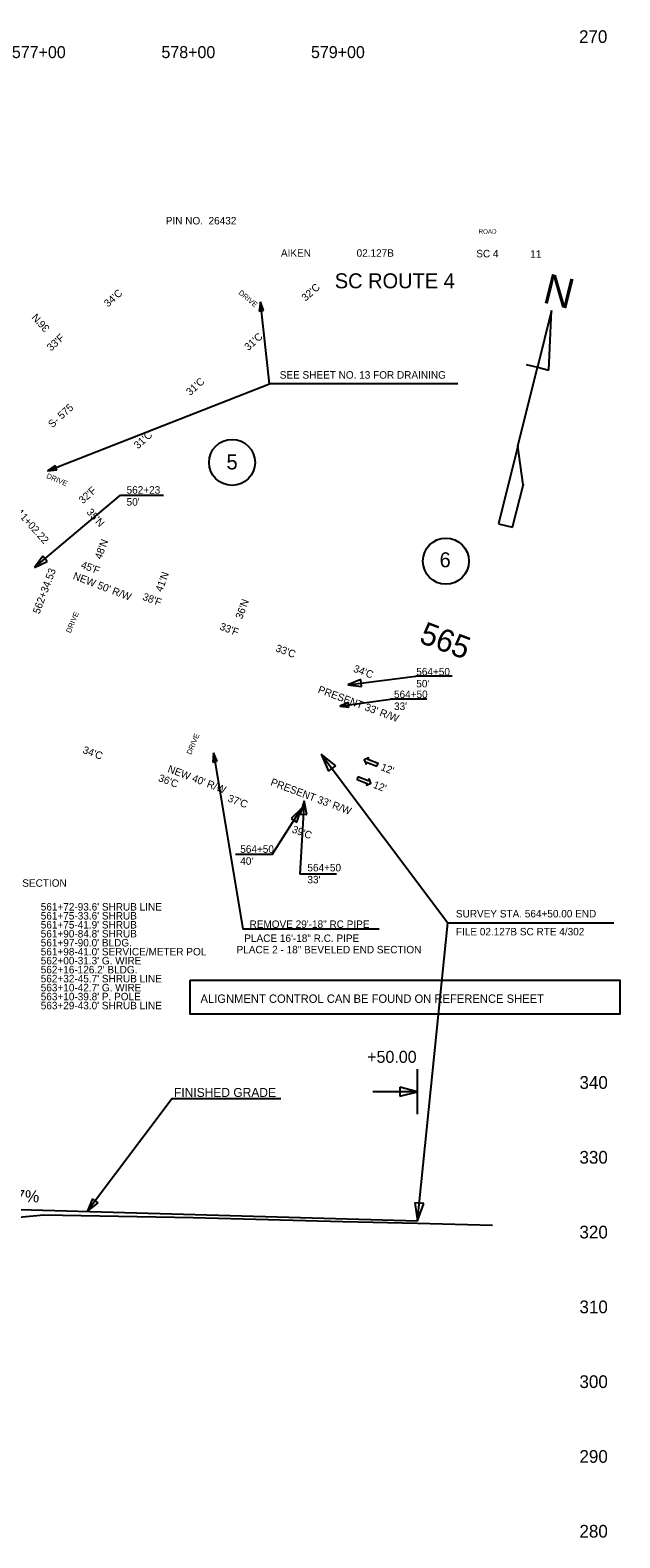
# Model space of a CAD drawing. Extents: x 48556 to 51363, y 45290 to 53458.
# Drawn here: x 50379 to 50773, y 51425 to 52433 of the extents above; entities that cross this region are included whole.
import ezdxf

# ---------------------------------------------------------------- set-up
doc = ezdxf.new("R2010")
doc.units = 0
for name, color, linetype in [('Level 1', 7, 'Continuous'), ('Level 12', 7, 'Continuous'), ('Level 14', 7, 'Continuous'), ('Level 19', 7, 'Continuous'), ('Level 2', 7, 'Continuous'), ('Level 20', 7, 'Continuous'), ('Level 21', 7, 'Continuous'), ('Level 24', 7, 'Continuous'), ('Level 25', 7, 'Continuous'), ('Level 29', 7, 'Continuous'), ('Level 33', 7, 'Continuous'), ('Level 40', 7, 'Continuous'), ('Level 41', 7, 'Continuous'), ('Level 42', 7, 'Continuous'), ('Level 45', 7, 'Continuous'), ('Level 48', 7, 'Continuous'), ('Level 6', 7, 'Continuous'), ('Level 8', 7, 'Continuous')]:
    doc.layers.add(name, color=color, linetype=linetype)

msp = doc.modelspace()

# ---------------------------------------------------------------- linework, layer by layer
at = {"layer": 'Level 1'}
for p, q in [((50573.5, 51948.5), (50658.2, 51835.8)), ((50637.9, 51636.5), (50658.2, 51835.8)), ((50658.2, 51835.8), (50769.1, 51835.8)), ((50637.9, 51707.9), (50637.9, 51737.9)), ((50473.7, 51718.3), (50417, 51642.7)), ((50473.7, 51718.3), (50546.5, 51718.3)), ((50637.9, 51722.9), (50607.9, 51722.9))]:
    msp.add_line(p, q, dxfattribs=at)
at = {"layer": 'Level 12'}
for centre in [(50513.8, 52143.6), (50656.8, 52077.6)]:
    msp.add_circle(centre, 15.4, dxfattribs=at)
at = {"layer": 'Level 14'}
for points in [[(50610.7, 51940.6), (50611.4, 51942.4), (50604.5, 51945), (50605, 51946.2), (50602.1, 51944.8), (50603.4, 51941.9), (50603.8, 51943.2)], [(50598, 51933.4), (50597.4, 51931.6), (50604.2, 51929), (50603.8, 51927.8), (50606.7, 51929.1), (50605.4, 51932.1), (50604.9, 51930.8)]]:
    msp.add_lwpolyline(points, close=True, dxfattribs=at)
at = {"layer": 'Level 2'}
for p, q in [((50727.5, 52245.2), (50718, 52207.2)), ((50725.6, 52205.3), (50727.5, 52245.2)), ((50727.5, 52245.2), (50727.5, 52245.2)), ((50704.8, 52154.4), (50718, 52207.2)), ((50710.4, 52209.1), (50718, 52207.2)), ((50718, 52207.2), (50725.6, 52205.3)), ((50725.6, 52205.3), (50725.7, 52205.7)), ((50704.8, 52154.4), (50691.9, 52102.6)), ((50708.5, 52128.7), (50704.8, 52154.4)), ((50701.4, 52100.2), (50708.6, 52129)), ((50708.6, 52129), (50708.5, 52128.7)), ((50691.9, 52102.6), (50701.4, 52100.2))]:
    msp.add_line(p, q, dxfattribs=at)
at = {"layer": 'Level 24'}
for p, q in [((50532.8, 52250.9), (50531.9, 52244.8)), ((50531.9, 52244.8), (50534.9, 52245.1)), ((50534.9, 52245.1), (50532.8, 52250.9)), ((50395.6, 52141.5), (50390.5, 52137.9)), ((50396.7, 52138.7), (50395.6, 52141.5)), ((50390.5, 52137.9), (50396.7, 52138.7)), ((50387.2, 52080.9), (50381.8, 52073.4)), ((50390.1, 52077.4), (50387.2, 52080.9)), ((50381.8, 52073.4), (50390.1, 52077.4)), ((50599.9, 51998.4), (50591.2, 51995)), ((50599.9, 51998.4), (50591.2, 51995)), ((50591.2, 51995), (50600.4, 51993.9)), ((50591.2, 51995), (50600.4, 51993.9)), ((50600.4, 51993.9), (50599.9, 51998.4)), ((50600.4, 51993.9), (50599.9, 51998.4)), ((50591.6, 51983), (50585.8, 51980.7)), ((50585.8, 51980.7), (50592, 51980)), ((50592, 51980), (50591.6, 51983)), ((50501.4, 51949.5), (50500.9, 51943.3)), ((50503.9, 51943.8), (50501.4, 51949.5)), ((50500.9, 51943.3), (50503.9, 51943.8)), ((50573.5, 51948.5), (50578.3, 51937.1)), ((50583.1, 51940.7), (50573.5, 51948.5)), ((50578.3, 51937.1), (50583.1, 51940.7)), ((50560.1, 51911.9), (50553.4, 51905.6)), ((50557.2, 51903.2), (50560.1, 51911.9)), ((50562.1, 51917.3), (50559.3, 51908.5)), ((50563.8, 51908.2), (50562.1, 51917.3)), ((50553.4, 51905.6), (50557.2, 51903.2)), ((50559.3, 51908.5), (50563.8, 51908.2)), ((50637.9, 51722.9), (50625.9, 51725.9)), ((50625.9, 51725.9), (50625.9, 51719.9)), ((50625.9, 51719.9), (50637.9, 51722.9)), ((50420.6, 51651.3), (50417, 51642.7)), ((50417, 51642.7), (50424.2, 51648.6)), ((50424.2, 51648.6), (50420.6, 51651.3)), ((50642.1, 51648.1), (50636.1, 51648.7)), ((50636.1, 51648.7), (50637.9, 51636.5)), ((50637.9, 51636.5), (50642.1, 51648.1))]:
    msp.add_line(p, q, dxfattribs=at)
at = {"layer": 'Level 25'}
msp.add_lwpolyline([(50485.8, 51797.4), (50773.1, 51797.4), (50773.1, 51774.7), (50485.8, 51774.7)], close=True, dxfattribs=at)
at = {"layer": 'Level 33'}
for p, q in [((50381.8, 52073.4), (50439.2, 52121.8)), ((50439.2, 52121.8), (50468, 52121.8)), ((50591.2, 51995), (50636.6, 52000.6)), ((50661, 52000.6), (50636.6, 52000.6)), ((50585.8, 51980.7), (50619.7, 51985.3)), ((50644.1, 51985.3), (50619.7, 51985.3)), ((50540.6, 51881.5), (50560.1, 51911.9)), ((50562.1, 51917.3), (50559.1, 51868.4)), ((50540.6, 51881.5), (50516.2, 51881.5)), ((50583.6, 51868.4), (50559.1, 51868.4))]:
    msp.add_line(p, q, dxfattribs=at)
at = {"layer": 'Level 40'}
msp.add_lwpolyline([(49737.9, 51618.4), (49787.9, 51629.6), (49837.9, 51637.9), (49887.9, 51643.8), (49937.9, 51647.2), (49987.9, 51648), (50037.9, 51647.7), (50087.9, 51654.7), (50137.9, 51645.6), (50187.9, 51644.3), (50237.9, 51643.2), (50287.9, 51642.5), (50305.6, 51639.5), (50351.8, 51637.3), (50387.9, 51640.6), (50437.9, 51639.7), (50487.9, 51638.8), (50537.9, 51637.5), (50587.9, 51636.2), (50637.9, 51635), (50687.9, 51633.7)], dxfattribs=at)
at = {"layer": 'Level 45'}
msp.add_line((50314.1, 51645.7), (50637.9, 51636.5), dxfattribs=at)
at = {"layer": 'Level 6'}
for p, q in [((50538.9, 52196.1), (50532.8, 52250.9)), ((50390.5, 52137.9), (50538.9, 52196.1)), ((50664.7, 52196.1), (50538.9, 52196.1)), ((50501.4, 51949.5), (50521.1, 51831.6)), ((50612.1, 51831.6), (50521.1, 51831.6))]:
    msp.add_line(p, q, dxfattribs=at)

# ---------------------------------------------------------------- texts
at = {"layer": 'Level 1'}
for p in [(50570.8, 51989.8), (50539.1, 51927.9)]:
    msp.add_text("PRESENT 33' R/W", height=5, rotation=339.4944, dxfattribs=at).set_placement(p)
for s, height, p in [('SURVEY STA. 564+50.00 END', 5, (50663.5, 51839.4)), ('FILE 02.127B SC RTE 4/302', 5, (50663.5, 51827.4)), ('+50.00', 8, (50604.2, 51742.2)), ('FINISHED GRADE', 6, (50475, 51719.4))]:
    msp.add_text(s, height=height, dxfattribs=at).set_placement(p)
at = {"layer": 'Level 12'}
for s, p in [('5', (50510.1, 52138.9)), ('6', (50652.6, 52073.5))]:
    msp.add_text(s, height=10, dxfattribs=at).set_placement(p)
at = {"layer": 'Level 19'}
msp.add_text('565', height=15, rotation=339.4944, dxfattribs=at).set_placement((50638.2, 52023.4))
at = {"layer": 'Level 2'}
msp.add_text('N', height=20, rotation=346, dxfattribs=at).set_placement((50720.7, 52250.7))
at = {"layer": 'Level 20'}
for s, rotation, p in [('11+02.22', 311.9794, (50369.3, 52109.6)), ('562+34.53', 69.4943, (50385, 52041.9)), ("12'", 339.1234, (50612.8, 51938)), ("12'", 339.1234, (50607.7, 51926.2))]:
    msp.add_text(s, height=5, rotation=rotation, dxfattribs=at).set_placement(p)
at = {"layer": 'Level 21'}
msp.add_text('S- 575', height=5, rotation=42.1456, dxfattribs=at).set_placement((50393.6, 52166.4))
at = {"layer": 'Level 24'}
for s, height, p in [('PIN NO.  26432', 5, (50469.5, 52302.7)), ('ROAD', 3, (50678.7, 52296.5)), ('AIKEN', 5, (50546.5, 52281.1)), ('02.127B', 5, (50597.1, 52281.1)), ('SC 4', 5, (50677.1, 52280.7)), ('11', 5, (50713.2, 52280.4)), ('SC ROUTE 4', 10, (50582.5, 52260)), ("561+72-93.6' SHRUB LINE", 5, (50385.9, 51844)), ("561+75-33.6' SHRUB", 5, (50385.9, 51838)), ("561+75-41.9' SHRUB", 5, (50385.9, 51832)), ("561+90-84.8' SHRUB", 5, (50385.9, 51826)), ("561+97-90.0' BLDG.", 5, (50385.9, 51820)), ("561+98-41.0' SERVICE/METER POL", 5, (50385.9, 51814)), ("562+00-31.3' G. WIRE", 5, (50385.9, 51808)), ("562+16-126.2' BLDG.", 5, (50385.9, 51802)), ("562+32-45.7' SHRUB LINE", 5, (50385.9, 51796)), ("563+10-42.7' G. WIRE", 5, (50385.9, 51790)), ("563+10-39.8' P. POLE", 5, (50385.9, 51784)), ("563+29-43.0' SHRUB LINE", 5, (50385.9, 51778))]:
    msp.add_text(s, height=height, dxfattribs=at).set_placement(p)
at = {"layer": 'Level 25'}
msp.add_text('ALIGNMENT CONTROL CAN BE FOUND ON REFERENCE SHEET', height=5.6, dxfattribs=at).set_placement((50492.7, 51782.3))
at = {"layer": 'Level 29'}
for s, p in [(' PLACE 2 - 18" BEVELED END SECTION', (50277.9, 51859.9)), (' PLACE 2 - 18" BEVELED END SECTION', (50515, 51815.4)), ('PLACE 16\'-18" R.C. PIPE', (50522, 51823))]:
    msp.add_text(s, height=5, dxfattribs=at).set_placement(p)
at = {"layer": 'Level 33'}
for s, p in [('562+23', (50443.3, 52122.7)), ("50'", (50443.3, 52114.7)), ('564+50', (50637, 52001.2)), ('564+50', (50622.1, 51986.1)), ("50'", (50637, 51993.2)), ("33'", (50622.1, 51978.1)), ("40'", (50519.3, 51874.6)), ('564+50', (50519.3, 51882.6)), ('564+50', (50564.2, 51870.2)), ("33'", (50564.2, 51862.2))]:
    msp.add_text(s, height=5, dxfattribs=at).set_placement(p)
for s, rotation, p in [("NEW 50' R/W", 338.9662, (50407, 52065.8)), ("NEW 40' R/W", 339.0399, (50470.3, 51936.8))]:
    msp.add_text(s, height=5, rotation=rotation, dxfattribs=at).set_placement(p)
at = {"layer": 'Level 41'}
msp.add_text('(-) 0.57%', height=8, rotation=358.3559, dxfattribs=at).set_placement((50340.8, 51650.1))
at = {"layer": 'Level 42'}
for s, height, p in [('270', 8.5, (50745.8, 52424)), ('577+00', 8, (50366.6, 52413.9)), ('578+00', 8, (50466.6, 52413.9)), ('579+00', 8, (50566.6, 52413.9)), ('340', 8.5, (50746.1, 51724.8)), ('330', 8.5, (50746.1, 51674.8)), ('320', 8.5, (50746.1, 51624.8)), ('310', 8.5, (50746.1, 51574.8)), ('300', 8.5, (50746.1, 51524.8)), ('290', 8.5, (50746.1, 51474.8)), ('280', 8.5, (50746.1, 51424.8))]:
    msp.add_text(s, height=height, dxfattribs=at).set_placement(p)
at = {"layer": 'Level 48'}
for s, rotation, p in [("32'C", 41.9793, (50563, 52251)), ("34'C", 41.9793, (50430.9, 52247.1)), ("36'N", 131.9793, (50392.2, 52233.5)), ("33'F", 41.9793, (50392.7, 52217.7)), ("31'C", 41.9793, (50524.7, 52218)), ("31'C", 41.9793, (50485.8, 52188)), ("31'C", 41.9793, (50450.9, 52152.3)), ("32'F", 41.9793, (50414, 52115.6)), ("35'N", 311.9793, (50416.2, 52110.1)), ("48'N", 69.4944, (50426.4, 52078.4)), ("45'F", 339.4944, (50412.3, 52073.2)), ("41'N", 69.4944, (50467, 52056.6)), ("38'F", 339.4944, (50453.5, 52051.9)), ("36'N", 69.4944, (50520.5, 52038.4)), ("33'F", 339.4944, (50505.1, 52032)), ("33'C", 339.4944, (50542.5, 52017.5)), ("34'C", 339.4944, (50594.5, 52003.8)), ("34'C", 339.4944, (50413.5, 51949.5)), ("36'C", 339.4944, (50464.1, 51930.7)), ("37'C", 339.4944, (50510.5, 51917.1)), ("39'C", 339.4944, (50553.4, 51896.4))]:
    msp.add_text(s, height=5, rotation=rotation, dxfattribs=at).set_placement(p)
at = {"layer": 'Level 6'}
for s, p in [('SEE SHEET NO. 13 FOR DRAINING', (50545.7, 52199.6)), ('REMOVE 29\'-18" RC PIPE', (50525.5, 51832.4))]:
    msp.add_text(s, height=5, dxfattribs=at).set_placement(p)
at = {"layer": 'Level 8'}
for rotation, p in [(320.1354, (50517.8, 52256.5)), (337.0664, (50389.3, 52133.3)), (67.0664, (50405.8, 52029.2)), (67.0664, (50486.4, 51947.9))]:
    msp.add_text('DRIVE', height=3.5, rotation=rotation, dxfattribs=at).set_placement(p)

doc.saveas('drawing.dxf')
